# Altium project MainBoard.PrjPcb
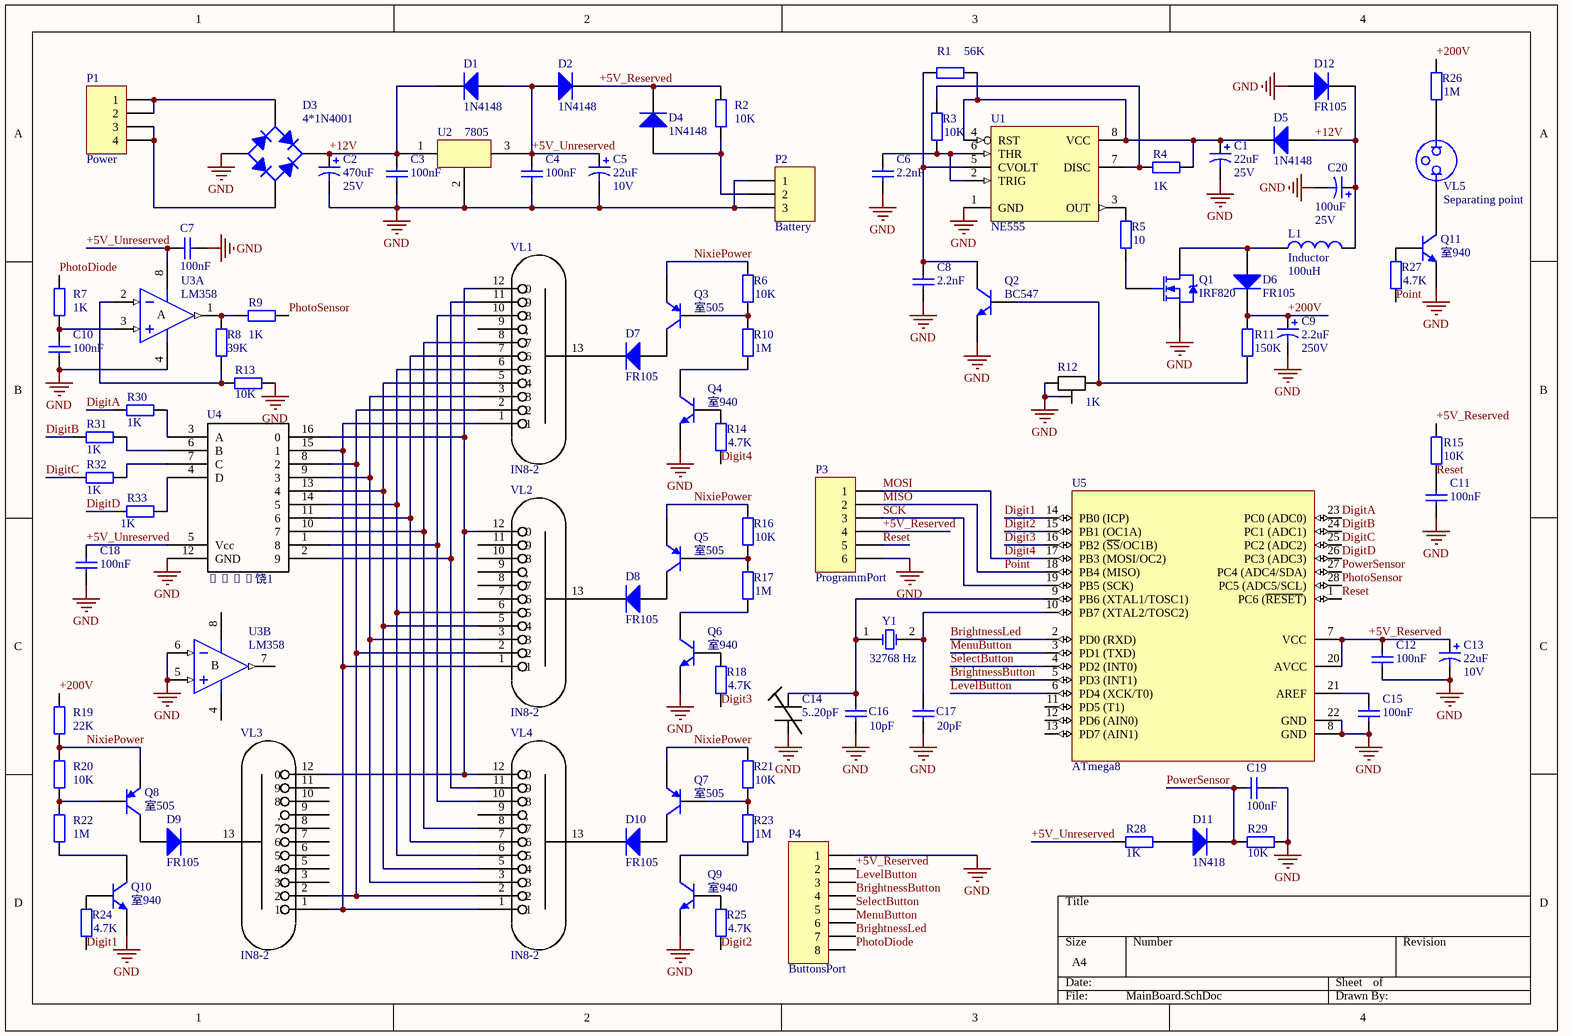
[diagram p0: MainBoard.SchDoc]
1 sheet, 92 parts. Net scope: global (net labels, ports and power ports of the same name join across sheets).

## Sheet MainBoard.SchDoc
size A4; PageSetup: Record=PageOptions|CenterHorizontal=True|CenterVertical=True|PrintScale=1.00|XCorrection=1.00|YCorrection=1.00|PrintKind=1|BorderSize=5000000|LeftOffset=0|BottomOffset=0|Orientation=2|PaperLength=1000|PaperWidth=1000|Scale=100|PaperSource=1|PrintQuality=300|MediaType=1|DitherType=10|PaperKind=A4|PrintScaleMode=1

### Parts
C1  25V  value 22uF  [RB7.6-15]
C2  25V  value 470uF  [RB7.6-15]
C3  value 100nF  [RAD-0.3]  (hidden comment: Cap)
C4  value 100nF  [RAD-0.3]  (hidden comment: Cap)
C5  10V  value 22uF  [RB7.6-15]
C6  value 2.2nF  [RAD-0.3]  (hidden comment: Cap)
C7  value 100nF  [RAD-0.3]  (hidden comment: Cap)
C8  value 2.2nF  [RAD-0.3]  (hidden comment: Cap)
C9  250V  value 2.2uF  [RB7.6-15]
C10  value 100nF  [RAD-0.3]  (hidden comment: Cap)
C11  value 100nF  [RAD-0.3]  (hidden comment: Cap)
C12  value 100nF  [RAD-0.3]  (hidden comment: Cap)
C13  10V  value 22uF  [RB7.6-15]
C14  5..20pF
C15  value 100nF  [RAD-0.3]  (hidden comment: Cap)
C16  value 10pF  [RAD-0.3]  (hidden comment: Cap)
C17  value 20pF  [RAD-0.3]  (hidden comment: Cap)
C18  value 100nF  [RAD-0.3]  (hidden comment: Cap)
C19  value 100nF  [RAD-0.3]  (hidden comment: Cap)
C20  25V  value 100uF  [RB7.6-15]
D1  1N4148  [DO-35]
D2  1N4148  [DO-35]
D3  4*1N4001  [D-38]
D4  1N4148  [DO-35]
D5  1N4148  [DO-35]
D6  FR105  [DO-35]
D7  FR105  [DO-41]
D8  FR105  [DO-41]
D9  FR105  [DO-41]
D10  FR105  [DO-41]
D11  1N418  [DO-41]
D12  FR105  [DO-41]
L1  Inductor  value 100uH  [0402-A]
P1  Power  [HDR1X4]
P2  Battery  [HDR1X3]
P3  ProgrammPort  [HDR1X6]
P4  ButtonsPort  [HDR1X8]
Q1  IRF820  [TO-220AB]
Q2  BC547  [TO-92A]
Q3  室505  [TO-92A]
Q4  室940  [TO-92A]
Q5  室505  [TO-92A]
Q6  室940  [TO-92A]
Q7  室505  [TO-92A]
Q8  室505  [TO-92A]
Q9  室940  [TO-92A]
Q10  室940  [TO-92A]
Q11  室940  [TO-92A]
R1  value 56K  [AXIAL-0.4]  (hidden comment: Res2)
R2  value 10K  [AXIAL-0.4]  (hidden comment: Res2)
R3  value 10K  [AXIAL-0.4]  (hidden comment: Res2)
R4  value 1K  [AXIAL-0.4]  (hidden comment: Res2)
R5  value 10  [AXIAL-0.4]  (hidden comment: Res2)
R6  value 10K  [AXIAL-0.4]  (hidden comment: Res2)
R7  value 1K  [AXIAL-0.4]  (hidden comment: Res2)
R8  value 39K  [AXIAL-0.4]  (hidden comment: Res2)
R9  value 1K  [AXIAL-0.4]  (hidden comment: Res2)
R10  value 1M  [AXIAL-0.4]  (hidden comment: Res2)
R11  value 150K  [AXIAL-0.4]  (hidden comment: Res2)
R12  1K
R13  value 10K  [AXIAL-0.4]  (hidden comment: Res2)
R14  value 4.7K  [AXIAL-0.4]  (hidden comment: Res2)
R15  value 10K  [AXIAL-0.4]  (hidden comment: Res2)
R16  value 10K  [AXIAL-0.4]  (hidden comment: Res2)
R17  value 1M  [AXIAL-0.4]  (hidden comment: Res2)
R18  value 4.7K  [AXIAL-0.4]  (hidden comment: Res2)
R19  value 22K  [AXIAL-0.4]  (hidden comment: Res2)
R20  value 10K  [AXIAL-0.4]  (hidden comment: Res2)
R21  value 10K  [AXIAL-0.4]  (hidden comment: Res2)
R22  value 1M  [AXIAL-0.4]  (hidden comment: Res2)
R23  value 1M  [AXIAL-0.4]  (hidden comment: Res2)
R24  value 4.7K  [AXIAL-0.4]  (hidden comment: Res2)
R25  value 4.7K  [AXIAL-0.4]  (hidden comment: Res2)
R26  value 1M  [AXIAL-0.4]  (hidden comment: Res2)
R27  value 4.7K  [AXIAL-0.4]  (hidden comment: Res2)
R28  value 1K  [AXIAL-0.4]  (hidden comment: Res2)
R29  value 10K  [AXIAL-0.4]  (hidden comment: Res2)
R30  value 1K  [AXIAL-0.4]  (hidden comment: Res2)
R31  value 1K  [AXIAL-0.4]  (hidden comment: Res2)
R32  value 1K  [AXIAL-0.4]  (hidden comment: Res2)
R33  value 1K  [AXIAL-0.4]  (hidden comment: Res2)
U1  NE555  [D008_N]
U2  7805
U3  LM358  [P008]  (parts A,B of 2)
U4  �155饶1
U5  ATmega8  [28P3]
VL1  IN8-2
VL2  IN8-2
VL3  IN8-2
VL4  IN8-2
VL5  Separating point  [PIN2]
Y1  32768 Hz  [R38]

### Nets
GND: C1.2 C2.2 C3.1 C4.1 C5.2 C6.1 C7.1 C8.1 C9.2 C10.1 C11.1 C12.1 C13.2 C14.1 C15.1 C16.1 C17.1 C18.1 C19.1 C20.2 D3.3(A) D12.1(A) P2.1 P2.3 P3.6 P4.1 Q1.3(S) Q2.1(E) Q4.1(E) Q6.1(E) Q9.1(E) Q10.1(E) Q11.1(E) R12.2 R12.3 R13.1 R29.1 U1.1(GND) U2.2(GND) U3.4(V-) U3.5(IN+) U3.6(IN-) U4.12(GND) U5.8(GND) U5.22(GND)
+5V_Reserved: C12.2 C13.1 D2.2(K) D4.2(K) P3.4 P4.2 R2.2 R15.2 U5.7(VCC) U5.20(AVCC)
+5V_Unreserved: C4.2 C5.1 C7.2 C18.2 D1.1(A) D2.1(A) R28.2 U2.3(Out) U3.8(V+) U4.5(Vcc)
+12V: C2.1 C3.2 C20.1 D1.2(K) D3.1(K) D5.1(A) D12.2(K) L1.2 U2.1(In)
+200V: C9.1 D6.2(K) R11.2 R19.2 R26.2
BrightnessButton: P4.4 U5.5(PD3_(INT1))
BrightnessLed: P4.7 U5.2(PD0_(RXD))
Digit1: R24.1 U5.14(PB0_(ICP))
Digit2: R25.1 U5.15(PB1_(OC1A))
Digit3: R18.1 U5.16(PB2_(~{SS}/OC1B))
Digit4: P3.1 R14.1 U5.17(PB3_(MOSI/OC2))  [also labelled MOSI]
DigitA: R30.1 U5.23(PC0_(ADC0))
DigitB: R31.1 U5.24(PC1_(ADC1))
DigitC: R32.1 U5.25(PC2_(ADC2))
DigitD: R33.1 U5.26(PC3_(ADC3))
LevelButton: P4.3 U5.6(PD4_(XCK/T0))
MenuButton: P4.6 U5.3(PD1_(TXD))
MISO: P3.2 R27.1 U5.18(PB4_(MISO))  [also labelled Point]
NixiePower: Q3.1(E) Q5.1(E) Q7.1(E) Q8.1(E) R6.2 R16.2 R19.1 R20.2 R21.2
PhotoDiode: P4.8 R7.2
PhotoSensor: R9.2 U5.28(PC5_(ADC5/SCL))
PowerSensor: C19.2 D11.2(K) R29.2 U5.27(PC4_(ADC4/SDA))
Reset: C11.2 P3.5 R15.1 U5.1(PC6_(~{RESET}))
SCK: P3.3 U5.19(PB5_(SCK))
SelectButton: P4.5 U5.4(PD2_(INT0))
NetC1_1: C1.1 D5.2(K) R1.2 R4.2 U1.4(RST) U1.8(VCC)
NetC6_2: C6.2 R3.1 U1.2(TRIG) U1.6(THR)
NetC8_2: C8.2 Q2.3(C) R1.1 U1.5(CVOLT)
NetC10_2: C10.2 R7.1 U3.3(IN+)
NetC14_2: C14.2 C16.2 U5.9(PB6_(XTAL1/TOSC1)) Y1.1(OSC1)
NetC15_2: C15.2 U5.21(AREF)
NetC17_2: C17.2 U5.10(PB7_(XTAL2/TOSC2)) Y1.2(OSC2)
NetD3_2: D3.2(C) P1.3 P1.4
NetD3_4: D3.4(C) P1.1 P1.2
NetD4_1: D4.1(A) P2.2 R2.1
NetD6_1: D6.1(A) L1.1 Q1.2(D)
NetD7_1: D7.1(A) Q3.3(C)
NetD7_2: D7.2(K) VL1.13
NetD8_1: D8.1(A) Q5.3(C)
NetD8_2: D8.2(K) VL2.13
NetD9_1: D9.1(A) Q8.3(C)
NetD9_2: D9.2(K) VL3.13
NetD10_1: D10.1(A) Q7.3(C)
NetD10_2: D10.2(K) VL4.13
NetD11_1: D11.1(A) R28.1
NetQ1_1: Q1.1(G) R5.1
NetQ2_2: Q2.2(B) R11.1 R12.1
NetQ3_2: Q3.2(B) R6.1 R10.2
NetQ4_2: Q4.2(B) R14.2
NetQ4_3: Q4.3(C) R10.1
NetQ5_2: Q5.2(B) R16.1 R17.2
NetQ6_2: Q6.2(B) R18.2
NetQ6_3: Q6.3(C) R17.1
NetQ7_2: Q7.2(B) R21.1 R23.2
NetQ8_2: Q8.2(B) R20.1 R22.2
NetQ9_2: Q9.2(B) R25.2
NetQ9_3: Q9.3(C) R23.1
NetQ10_2: Q10.2(B) R24.2
NetQ10_3: Q10.3(C) R22.1
NetQ11_2: Q11.2(B) R27.2
NetQ11_3: Q11.3(C) VL5.1
NetR3_2: R3.2 R4.1 U1.7(DISC)
NetR5_2: R5.2 U1.3(OUT)
NetR8_1: R8.1 R13.2 U3.2(IN-)
NetR8_2: R8.2 R9.1 U3.1(OUT)
NetR26_1: R26.1 VL5.2
NetR30_2: R30.2 U4.3(A)
NetR31_2: R31.2 U4.6(B)
NetR32_2: R32.2 U4.7(C)
NetR33_2: R33.2 U4.4(D)
NetU4_1: U4.1(8) VL1.10(8) VL4.10(8)
NetU4_2: U4.2(9) VL1.11(9) VL4.11(9)
NetU4_8: U4.8(2) VL1.2 VL2.2 VL3.2 VL4.2
NetU4_9: U4.9(3) VL1.3 VL2.3 VL4.3
NetU4_10: U4.10(7) VL1.8(7) VL4.8(7)
NetU4_11: U4.11(6) VL1.7(6) VL4.7(6)
NetU4_13: U4.13(4) VL1.5(4) VL2.5(4) VL4.5(4)
NetU4_14: U4.14(5) VL1.6(5) VL2.6(5) VL4.6(5)
NetU4_15: U4.15(1) VL1.1 VL2.1 VL3.1 VL4.1
NetU4_16: U4.16(0) VL1.12(0) VL2.12(0) VL3.12(0) VL4.12(0)

Not connected (* = marked no-connect by the designer): U3 7(OUT); U5 11(PD5_(T1)) 12(PD6_(AIN0)) 13(PD7_(AIN1)); VL1 9(,); VL2 7(6) 8(7) 9(,) 10(8) 11(9); VL3 3 5(4) 6(5) 7(6) 8(7) 9(,) 10(8) 11(9); VL4 9(,)

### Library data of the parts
C1 C2 C5 C9 C13 C20 = Cap Pol1: Polarized Capacitor (Radial)
C3 C4 C6-C8 C10-C12 C15-C19 = Cap: Capacitor
C14 = Trimmer_cap
D1 D2 D4-D6 = Diode 1N4148: High Conductance Fast Diode
D3 = Bridge1: Full Wave Diode Bridge
D7-D12 = Diode 1N4007: 1 Amp General Purpose Rectifier
L1 = Inductor: Code_IEC: 1005
P1 = Header 4: Header, 4-Pin
P2 = Header 3: Header, 3-Pin
P3 = Header 6: Header, 6-Pin
P4 = Header 8: Header, 8-Pin
Q1 = IRF820: HEXFET N-Channel Power MOSFET; Note: Pin 2 is electrically connected to pin 4.
Q2 Q4 Q6 Q9-Q11 = 2N3904: NPN General Purpose Amplifier
Q3 Q5 Q7 Q8 = 2N3906: PNP General Purpose Amplifier
R1-R11 R13-R33 = Res2: Resistor
R12 = Trimmer_res
U1 = NE555D: Precision Timer
U3 = LM358P: Dual Operational Amplifier
U4 = 155ID1
U5 = ATmega8A-PU: 8-bit AVR Microcontroller, 8KB Flash, 512 Bytes EEPROM, 1KB SRAM, 28-pin PDIP, Industrial Grade (-40°C to 85°C)
VL5 = Lamp Neon: Neon Lamp
Y1 = XTAL: Crystal Oscillator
